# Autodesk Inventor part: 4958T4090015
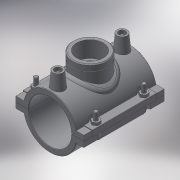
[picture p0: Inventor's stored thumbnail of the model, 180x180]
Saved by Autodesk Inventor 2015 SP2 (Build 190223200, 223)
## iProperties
Created: 2017-07
Part Number: 4958T4090015
Material: Generic
Description: PLASSON SADDLE 90X1.1/2" FEMALE BSPP
Document SubType Name: Modeling
Designer: KIM
Density: 1 g/cm^3
Appearance: Default
Author: KIM
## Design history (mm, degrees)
derived "4958T4.ipt"
feature "Solid1::4958T4.ipt"
tag "TaggingFeature1"
body "Solid1"
other parameters: "d1" = 112.5, "d2" = 126, "d3" = 22.5, "d4" = 118, "d5" = 0, "d6" = 0.1, "d8" = 0, "d19" = 6, "d20" = 6, "d21" = 70.8, "d23" = 0, "d24" = 35.4, "d26" = 0, "d27" = 3, "d28" = 3, "d29" = 3, "d30" = 24.00694, "d31" = 6, "d32" = 0, "d33" = 0, "d34" = 0.6, "d40" = 60.3, "d43" = 0, "d45" = 0, "d46" = 9, "d47" = 75, "d48" = 58.2985, "d50" = 0, "d51" = 44.845, "d52" = 24, "d53" = 0, "d54" = 35.876, "d56" = 0, "d57" = -9, "d58" = 0.5, "d59" = 0.1, "d60" = 0, "d61" = 0.5, "d64" = 1.34535, "d67" = 0.9, "d70" = 15, "d72" = 0, "d73" = 6, "d75" = 5, "d76" = 0, "d77" = 4.5, "d78" = 74, "d79" = 15, "d80" = 47.2, "d82" = 5 deg, "d84" = 4, "d85" = 14, "d86" = 0, "d87" = 3, "d88" = 0, "d89" = 1, "d90" = 1, "d91" = 94.4, "d92" = 0, "d93" = 0.5, "d94" = 47.36842, "Rp_" = 44.845, "B_" = 126, "L_" = 118, "d_t" = 6
